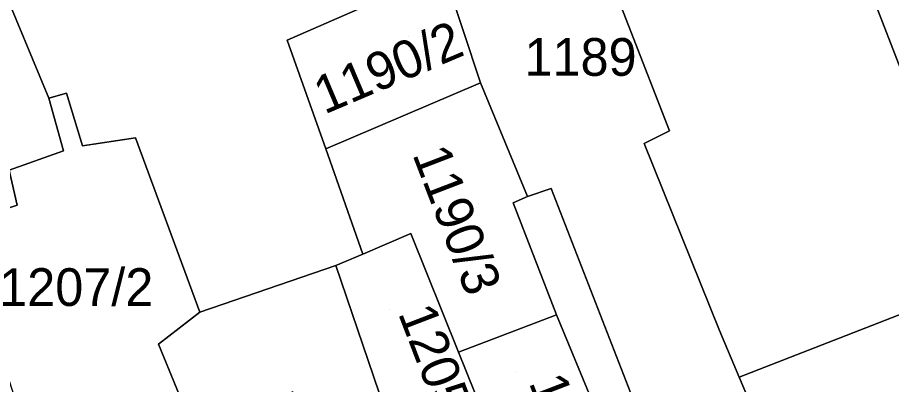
# Model space of a CAD drawing. Extents: x -263943 to -261149, y -1236934 to -1230686.
# Drawn here: x -262965.33 to -262918.94, y -1235385.35 to -1235365.9 of the extents above; entities that cross this region are included whole.
import ezdxf

# ---------------------------------------------------------------- set-up
doc = ezdxf.new("R2010")
doc.units = 0
for name, color, linetype in [('body_kn', 7, 'Continuous'), ('kladpar_druhypozemkov', 7, 'Continuous'), ('kladpar_hranice', 7, 'Continuous'), ('kladpar_parcelnecisla', 7, 'Continuous'), ('kladpar_plochy', 7, 'Continuous')]:
    doc.layers.add(name, color=color, linetype=linetype)

msp = doc.modelspace()

# ---------------------------------------------------------------- linework, layer by layer
at = {"layer": 'body_kn'}
for p, q in [((-262951.02, -1235367.1), (-262951.02, -1235367.1)), ((-262951.02, -1235367.1), (-262951.02, -1235367.1)), ((-262940.75, -1235369.37), (-262940.75, -1235369.37)), ((-262940.75, -1235369.37), (-262940.75, -1235369.37)), ((-262963.66, -1235370.17), (-262963.66, -1235370.17)), ((-262962.73, -1235369.91), (-262962.73, -1235369.91)), ((-262930.73, -1235371.9), (-262930.73, -1235371.9)), ((-262959.07, -1235372.28), (-262959.07, -1235372.28)), ((-262962.89, -1235372.96), (-262962.89, -1235372.96)), ((-262962.89, -1235372.96), (-262962.89, -1235372.96)), ((-262961.87, -1235372.71), (-262961.87, -1235372.71)), ((-262948.97, -1235372.86), (-262948.97, -1235372.86)), ((-262932.08, -1235372.58), (-262932.08, -1235372.58)), ((-262937, -1235374.96), (-262937, -1235374.96)), ((-262939.03, -1235375.73), (-262939.03, -1235375.73)), ((-262938.27, -1235375.39), (-262938.27, -1235375.39)), ((-262944.46, -1235377.35), (-262944.46, -1235377.35)), ((-262947, -1235378.45), (-262947, -1235378.45)), ((-262948.44, -1235379.05), (-262948.44, -1235379.05)), ((-262948.44, -1235379.05), (-262948.44, -1235379.05)), ((-262955.65, -1235381.52), (-262955.65, -1235381.52)), ((-262936.73, -1235381.66), (-262936.73, -1235381.66)), ((-262936.73, -1235381.66), (-262936.73, -1235381.66)), ((-262928.07, -1235382.5), (-262928.07, -1235382.5)), ((-262928.07, -1235382.5), (-262928.07, -1235382.5)), ((-262957.85, -1235383.22), (-262957.85, -1235383.22)), ((-262941.92, -1235383.64), (-262941.92, -1235383.64)), ((-262927.03, -1235384.96), (-262927.03, -1235384.96))]:
    msp.add_line(p, q, dxfattribs=at)
at = {"layer": 'kladpar_druhypozemkov'}
for p, q in [((-262944.6, -1235366.89), (-262944.6, -1235366.89)), ((-262936.2, -1235367.1), (-262936.2, -1235367.1)), ((-262940.88, -1235375.74), (-262940.88, -1235375.74)), ((-262961.09, -1235379.41), (-262961.09, -1235379.41)), ((-262945.6, -1235381.39), (-262945.6, -1235381.39)), ((-262938.9, -1235384.69), (-262938.9, -1235384.69))]:
    msp.add_line(p, q, dxfattribs=at)
at = {"layer": 'kladpar_hranice'}
for points in [[(-262903.33, -1235397.38), (-262901.79, -1235401.87), (-262904.86, -1235403.09), (-262905.58, -1235401.37), (-262906.47, -1235399.25), (-262907.82, -1235399.68), (-262909.1, -1235396.03), (-262910.99, -1235390.87), (-262910.22, -1235390.61), (-262913.9, -1235381.88), (-262912.96, -1235381.54), (-262913.59, -1235379.73), (-262915.36, -1235374.68), (-262916.04, -1235374.85), (-262924.32, -1235353.5), (-262935.86, -1235323.3), (-262938.41, -1235316.63), (-262934.34, -1235315.61), (-262930.52, -1235327.14), (-262922.03, -1235352.73), (-262906.41, -1235389.16), (-262903.61, -1235388.14), (-262900.7, -1235396.44), (-262903.33, -1235397.38)], [(-262951.02, -1235367.1), (-262948.97, -1235372.86), (-262947, -1235378.45), (-262948.44, -1235379.05), (-262955.65, -1235381.52), (-262959.07, -1235372.28), (-262961.87, -1235372.71), (-262962.73, -1235369.91), (-262963.66, -1235370.17), (-262968.02, -1235359.74), (-262967.25, -1235359.32), (-262977.61, -1235320.74), (-262964.37, -1235320.47), (-262954.46, -1235350.99), (-262952.93, -1235350.82), (-262947.29, -1235365.48), (-262951.02, -1235367.1)], [(-262962.89, -1235372.96), (-262965.77, -1235373.99), (-262965.34, -1235375.85), (-262968.48, -1235376.87), (-262970.71, -1235369.75), (-262976.6, -1235354.75), (-262986.01, -1235321.6), (-262977.61, -1235320.74), (-262967.25, -1235359.32), (-262968.02, -1235359.74), (-262963.66, -1235370.17), (-262962.89, -1235372.96)], [(-262928.07, -1235382.5), (-262932.08, -1235372.58), (-262930.73, -1235371.9), (-262935.08, -1235360.72), (-262936.27, -1235361.14), (-262949.25, -1235327.15), (-262935.86, -1235323.3), (-262924.32, -1235353.5), (-262916.04, -1235374.85), (-262915.36, -1235374.68), (-262913.59, -1235379.73), (-262927.03, -1235384.96), (-262928.07, -1235382.5)], [(-262935.08, -1235360.72), (-262930.73, -1235371.9), (-262932.08, -1235372.58), (-262928.07, -1235382.5)], [(-262940.75, -1235369.37), (-262948.97, -1235372.86), (-262951.02, -1235367.1), (-262947.29, -1235365.48), (-262945.85, -1235364.97), (-262942.63, -1235363.69), (-262940.75, -1235369.37)], [(-262928.07, -1235382.5), (-262927.03, -1235384.96), (-262918.75, -1235404.44), (-262916.37, -1235410.76), (-262915.11, -1235414.1), (-262913.82, -1235417.51), (-262911.74, -1235423.02), (-262909.88, -1235427.97), (-262908.94, -1235430.48), (-262909.5, -1235430.69), (-262913.08, -1235432.07), (-262921.88, -1235409.02), (-262923.32, -1235409.62), (-262928.96, -1235395.64), (-262937, -1235374.96), (-262938.27, -1235375.39), (-262940.75, -1235369.37), (-262942.63, -1235363.69)], [(-262936.73, -1235381.66), (-262941.92, -1235383.64), (-262944.46, -1235377.35), (-262947, -1235378.45), (-262948.97, -1235372.86), (-262940.75, -1235369.37), (-262938.27, -1235375.39), (-262939.03, -1235375.73), (-262936.73, -1235381.66)], [(-262955.89, -1235387.96), (-262957.67, -1235388.73), (-262953.31, -1235399.32), (-262952.12, -1235398.9), (-262949.99, -1235402.62), (-262955.16, -1235404.33), (-262957.11, -1235404.5), (-262957.97, -1235402.55), (-262964.47, -1235386.03), (-262965.31, -1235386.54), (-262968.48, -1235376.87), (-262965.34, -1235375.85), (-262965.77, -1235373.99), (-262962.89, -1235372.96), (-262963.66, -1235370.17), (-262962.73, -1235369.91), (-262961.87, -1235372.71), (-262959.07, -1235372.28), (-262955.65, -1235381.52), (-262957.85, -1235383.22), (-262955.89, -1235387.96)], [(-262919.14, -1235424.34), (-262921.6, -1235417.5), (-262921.85, -1235417.59), (-262927.17, -1235404.74), (-262932.66, -1235391.49), (-262936.73, -1235381.66), (-262939.03, -1235375.73), (-262938.27, -1235375.39), (-262937, -1235374.96), (-262928.96, -1235395.64), (-262923.32, -1235409.62), (-262921.88, -1235409.02), (-262913.08, -1235432.07)], [(-262948.44, -1235379.05), (-262947, -1235378.45), (-262944.46, -1235377.35), (-262941.92, -1235383.64), (-262939.78, -1235388.95), (-262944.42, -1235390.83), (-262948.44, -1235379.05)], [(-262940.33, -1235426.43), (-262945.29, -1235414.32), (-262945.85, -1235412.91), (-262941.48, -1235411.17), (-262944.13, -1235404.23), (-262946.19, -1235396.26), (-262950.72, -1235385.75), (-262955.89, -1235387.96), (-262957.85, -1235383.22), (-262955.65, -1235381.52), (-262948.44, -1235379.05), (-262944.42, -1235390.83), (-262940.08, -1235403.34), (-262937.75, -1235410.07), (-262938.14, -1235410.23), (-262935.56, -1235417.4)], [(-262914.01, -1235402.57), (-262918.75, -1235404.44), (-262927.03, -1235384.96), (-262913.59, -1235379.73), (-262912.96, -1235381.54), (-262913.9, -1235381.88), (-262910.22, -1235390.61), (-262910.99, -1235390.87), (-262909.1, -1235396.03), (-262907.82, -1235399.68), (-262906.47, -1235399.25), (-262905.58, -1235401.37), (-262904.86, -1235403.09), (-262902.63, -1235408.44), (-262907.5, -1235410.39), (-262910.34, -1235403.37), (-262911.15, -1235401.37), (-262914.01, -1235402.57)], [(-262939.78, -1235388.95), (-262941.92, -1235383.64), (-262936.73, -1235381.66), (-262932.66, -1235391.49), (-262937.89, -1235393.64), (-262939.78, -1235388.95)]]:
    msp.add_lwpolyline(points, dxfattribs=at)
at = {"layer": 'kladpar_plochy'}
for points in [[(-262903.33, -1235397.38), (-262901.79, -1235401.87), (-262904.86, -1235403.09), (-262905.58, -1235401.37), (-262906.47, -1235399.25), (-262907.82, -1235399.68), (-262909.1, -1235396.03), (-262910.99, -1235390.87), (-262910.22, -1235390.61), (-262913.9, -1235381.88), (-262912.96, -1235381.54), (-262913.59, -1235379.73), (-262915.36, -1235374.68), (-262916.04, -1235374.85), (-262924.32, -1235353.5), (-262935.86, -1235323.3), (-262938.41, -1235316.63), (-262934.34, -1235315.61), (-262930.52, -1235327.14), (-262922.03, -1235352.73), (-262906.41, -1235389.16), (-262903.61, -1235388.14), (-262900.7, -1235396.44)], [(-262951.02, -1235367.1), (-262948.97, -1235372.86), (-262947, -1235378.45), (-262948.44, -1235379.05), (-262955.65, -1235381.52), (-262959.07, -1235372.28), (-262961.87, -1235372.71), (-262962.73, -1235369.91), (-262963.66, -1235370.17), (-262968.02, -1235359.74), (-262967.25, -1235359.32), (-262977.61, -1235320.74), (-262964.37, -1235320.47), (-262954.46, -1235350.99), (-262952.93, -1235350.82), (-262947.29, -1235365.48)], [(-262962.89, -1235372.96), (-262965.77, -1235373.99), (-262965.34, -1235375.85), (-262968.48, -1235376.87), (-262970.71, -1235369.75), (-262976.6, -1235354.75), (-262986.01, -1235321.6), (-262977.61, -1235320.74), (-262967.25, -1235359.32), (-262968.02, -1235359.74), (-262963.66, -1235370.17)], [(-262928.07, -1235382.5), (-262932.08, -1235372.58), (-262930.73, -1235371.9), (-262935.08, -1235360.72), (-262936.27, -1235361.14), (-262949.25, -1235327.15), (-262935.86, -1235323.3), (-262924.32, -1235353.5), (-262916.04, -1235374.85), (-262915.36, -1235374.68), (-262913.59, -1235379.73), (-262927.03, -1235384.96)], [(-262940.75, -1235369.37), (-262948.97, -1235372.86), (-262951.02, -1235367.1), (-262947.29, -1235365.48), (-262945.85, -1235364.97), (-262942.63, -1235363.69)], [(-262936.73, -1235381.66), (-262941.92, -1235383.64), (-262944.46, -1235377.35), (-262947, -1235378.45), (-262948.97, -1235372.86), (-262940.75, -1235369.37), (-262938.27, -1235375.39), (-262939.03, -1235375.73)], [(-262955.89, -1235387.96), (-262957.67, -1235388.73), (-262953.31, -1235399.32), (-262952.12, -1235398.9), (-262949.99, -1235402.62), (-262955.16, -1235404.33), (-262957.11, -1235404.5), (-262957.97, -1235402.55), (-262964.47, -1235386.03), (-262965.31, -1235386.54), (-262968.48, -1235376.87), (-262965.34, -1235375.85), (-262965.77, -1235373.99), (-262962.89, -1235372.96), (-262963.66, -1235370.17), (-262962.73, -1235369.91), (-262961.87, -1235372.71), (-262959.07, -1235372.28), (-262955.65, -1235381.52), (-262957.85, -1235383.22)], [(-262948.44, -1235379.05), (-262947, -1235378.45), (-262944.46, -1235377.35), (-262941.92, -1235383.64), (-262939.78, -1235388.95), (-262944.42, -1235390.83)], [(-262914.01, -1235402.57), (-262918.75, -1235404.44), (-262927.03, -1235384.96), (-262913.59, -1235379.73), (-262912.96, -1235381.54), (-262913.9, -1235381.88), (-262910.22, -1235390.61), (-262910.99, -1235390.87), (-262909.1, -1235396.03), (-262907.82, -1235399.68), (-262906.47, -1235399.25), (-262905.58, -1235401.37), (-262904.86, -1235403.09), (-262902.63, -1235408.44), (-262907.5, -1235410.39), (-262910.34, -1235403.37), (-262911.15, -1235401.37)], [(-262939.78, -1235388.95), (-262941.92, -1235383.64), (-262936.73, -1235381.66), (-262932.66, -1235391.49), (-262937.89, -1235393.64)]]:
    msp.add_lwpolyline(points, close=True, dxfattribs=at)
for points in [[(-262935.08, -1235360.72), (-262930.73, -1235371.9), (-262932.08, -1235372.58), (-262928.07, -1235382.5), (-262927.03, -1235384.96), (-262918.75, -1235404.44), (-262916.37, -1235410.76), (-262915.11, -1235414.1), (-262913.82, -1235417.51), (-262911.74, -1235423.02), (-262909.88, -1235427.97), (-262908.94, -1235430.48), (-262909.5, -1235430.69), (-262913.08, -1235432.07), (-262921.88, -1235409.02), (-262923.32, -1235409.62), (-262928.96, -1235395.64), (-262937, -1235374.96), (-262938.27, -1235375.39), (-262940.75, -1235369.37), (-262942.63, -1235363.69)], [(-262919.14, -1235424.34), (-262921.6, -1235417.5), (-262921.85, -1235417.59), (-262927.17, -1235404.74), (-262932.66, -1235391.49), (-262936.73, -1235381.66), (-262939.03, -1235375.73), (-262938.27, -1235375.39), (-262937, -1235374.96), (-262928.96, -1235395.64), (-262923.32, -1235409.62), (-262921.88, -1235409.02), (-262913.08, -1235432.07)], [(-262940.33, -1235426.43), (-262945.29, -1235414.32), (-262945.85, -1235412.91), (-262941.48, -1235411.17), (-262944.13, -1235404.23), (-262946.19, -1235396.26), (-262950.72, -1235385.75), (-262955.89, -1235387.96), (-262957.85, -1235383.22), (-262955.65, -1235381.52), (-262948.44, -1235379.05), (-262944.42, -1235390.83), (-262940.08, -1235403.34), (-262937.75, -1235410.07), (-262938.14, -1235410.23), (-262935.56, -1235417.4), (-262933.57, -1235422.92)]]:
    msp.add_lwpolyline(points, dxfattribs=at)

# ---------------------------------------------------------------- texts
at = {"layer": 'kladpar_parcelnecisla'}
for s, rotation, p in [('1190/2', 23, (-262949.039, -1235371.052)), ('1190/3', 291, (-262944.386, -1235373.15)), ('1205/2', 291, (-262945.148, -1235381.57)), ('1190/4', 291, (-262938.209, -1235385.246))]:
    msp.add_text(s, height=2, rotation=rotation, dxfattribs=at).set_placement(p)
for s, p in [('1189', (-262938.423, -1235368.99)), ('1207/2', (-262966.298, -1235381.19))]:
    msp.add_text(s, height=2, dxfattribs=at).set_placement(p)

doc.saveas('drawing.dxf')
